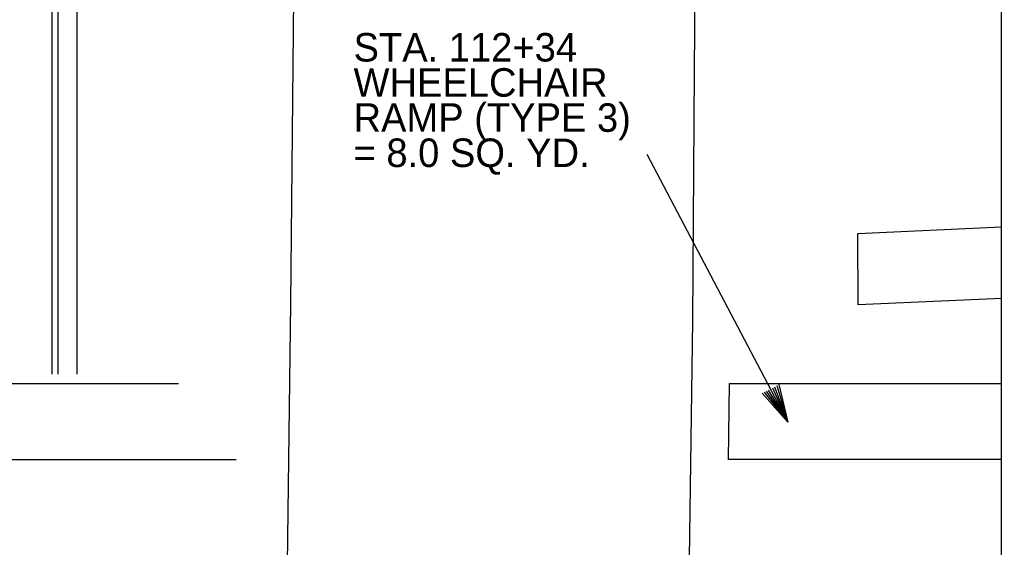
# Model space of a CAD drawing. Extents: x 1944905 to 1956777, y 763871 to 764977.
# Drawn here: x 1949424 to 1949941, y 764148 to 764426 of the extents above; entities that cross this region are included whole.
import ezdxf

# ---------------------------------------------------------------- set-up
doc = ezdxf.new("R2010")
doc.units = 0
for name, color, linetype in [('A_Sidewalk', 7, 'Continuous'), ('Default', 7, 'Continuous'), ('R_Water', 7, 'Continuous'), ('S_CROSS_DRAIN', 7, 'Continuous'), ('S_EDGE_PAVEMENT', 7, 'Continuous')]:
    doc.layers.add(name, color=color, linetype=linetype)

msp = doc.modelspace()

# ---------------------------------------------------------------- linework, layer by layer
at = {"layer": 'A_Sidewalk'}
for p, q in [((1949342.94, 764234.61), (1949507.88, 764234.61)), ((1949384.05, 764194.61), (1949538.21, 764194.61))]:
    msp.add_line(p, q, dxfattribs=at)
msp.add_lwpolyline([(1949941.01, 764194.61), (1949797.42, 764194.61), (1949797.89, 764234.61), (1949941.01, 764234.61)], dxfattribs=at)
at = {"layer": 'Default'}
for p, q in [((1949941.01, 763910.07), (1949941.01, 764937.29)), ((1949754.31, 764355.43), (1949828.66, 764214.29)), ((1949823.85, 764234.16), (1949828.66, 764214.29)), ((1949815, 764229.5), (1949828.66, 764214.29)), ((1949816.11, 764230.08), (1949828.66, 764214.29)), ((1949817.21, 764230.66), (1949828.66, 764214.29)), ((1949818.32, 764231.24), (1949828.66, 764214.29)), ((1949820.53, 764232.41), (1949828.66, 764214.29)), ((1949821.64, 764232.99), (1949828.66, 764214.29)), ((1949822.74, 764233.57), (1949828.66, 764214.29))]:
    msp.add_line(p, q, dxfattribs=at)
msp.add_lwpolyline([(1949941.01, 764279.49), (1949865.65, 764276.15), (1949865.48, 764313.67), (1949941.01, 764317.15)], dxfattribs=at)
at = {"layer": 'R_Water'}
for p, q in [((1949444.55, 764239.61), (1949444.55, 764390.44)), ((1949454.55, 764239.61), (1949454.55, 764390.44)), ((1949441.26, 764239.61), (1949441.26, 764388.17))]:
    msp.add_line(p, q, dxfattribs=at)
at = {"layer": 'S_CROSS_DRAIN'}
for p, q in [((1949441.26, 764388.17), (1949441.26, 764680.26)), ((1949444.55, 764390.44), (1949444.55, 764680.26)), ((1949454.55, 764390.44), (1949454.55, 764680.26))]:
    msp.add_line(p, q, dxfattribs=at)
at = {"layer": 'S_EDGE_PAVEMENT'}
for points in [[(1949563.8, 764022.9), (1949564.74, 764098.49), (1949566.96, 764276.97), (1949568.19, 764402.15), (1949569.42, 764527.32), (1949570.65, 764652.49), (1949571.88, 764777.67), (1949573.46, 764887.95)], [(1949773.62, 763910.07), (1949775.95, 764080.27), (1949778.51, 764267.61), (1949779.53, 764399.29), (1949780.54, 764530.97), (1949779.91, 764702.99), (1949781.3, 764840.56), (1949781.63, 764873.29)]]:
    msp.add_lwpolyline(points, dxfattribs=at)

# ---------------------------------------------------------------- texts
at = {"layer": 'Default'}
for s, p in [('STA. 112+34', (1949599.97, 764404.13)), ('WHEELCHAIR', (1949599.97, 764385.63)), ('RAMP (TYPE 3)', (1949599.97, 764367.13)), ('= 8.0 SQ. YD.', (1949599.97, 764348.62))]:
    msp.add_text(s, height=15, dxfattribs=at).set_placement(p)

doc.saveas('drawing.dxf')
